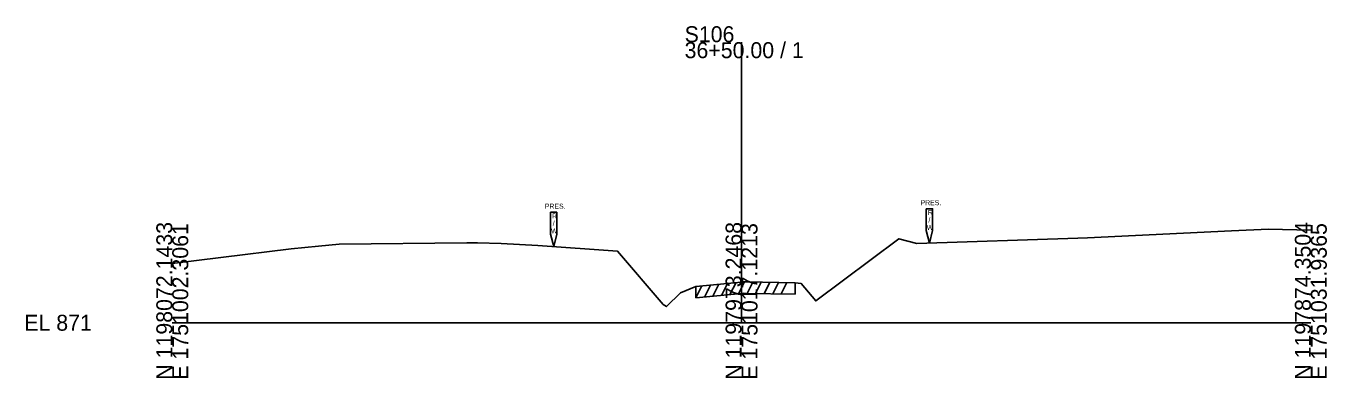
# Model space of a CAD drawing. Extents: x -26 to 1203, y -10 to 19527.
# Drawn here: x 974.3 to 1202.8, y 2990.3 to 3052.1 of the extents above; entities that cross this region are included whole.
import ezdxf

# ---------------------------------------------------------------- set-up
doc = ezdxf.new("R2010")
doc.units = 0
for name, color, linetype in [('RD_GPK_XS_Cell', 7, 'Continuous'), ('RD_XS_ExGround', 7, 'Continuous'), ('RD_XS_ExPaveRet', 7, 'Continuous'), ('RD_XS_ExRW', 7, 'Continuous'), ('RD_XS_TX_Elev_EX', 7, 'Continuous')]:
    doc.layers.add(name, color=color, linetype=linetype)

msp = doc.modelspace()

# ---------------------------------------------------------------- linework, layer by layer
at = {"layer": 'RD_GPK_XS_Cell'}
for p, q in [((1100, 3000), (1100, 3049.24)), ((1000, 3000), (1100, 3000)), ((1100, 3000), (1200, 3000))]:
    msp.add_line(p, q, dxfattribs=at)
at = {"layer": 'RD_XS_ExGround'}
msp.add_lwpolyline([(1000, 3010.38), (1008.53, 3011.43), (1020.91, 3012.95), (1025.68, 3013.45), (1029.32, 3013.81), (1051.72, 3014.03), (1053.59, 3014.05), (1057.8, 3013.88), (1064.23, 3013.58), (1078.23, 3012.54), (1086.25, 3003.23), (1086.79, 3002.85), (1089.26, 3005.23), (1091.97, 3006.36), (1100, 3007.13), (1100.36, 3007.17), (1100.79, 3007.16), (1109.43, 3007.02), (1110.49, 3006.88), (1113.04, 3003.83), (1127.63, 3014.75), (1130.81, 3013.91), (1159.05, 3014.87), (1160.78, 3014.92), (1186.06, 3016.11), (1192.56, 3016.4), (1200, 3016.27)], dxfattribs=at)
at = {"layer": 'RD_XS_ExPaveRet'}
for p, q in [((1091.97, 3004.36), (1093.03, 3006.46)), ((1091.97, 3004.36), (1091.97, 3006.36)), ((1093.47, 3004.5), (1094.53, 3006.6)), ((1094.97, 3004.65), (1096.03, 3006.75)), ((1096.47, 3004.79), (1097.53, 3006.89)), ((1097.97, 3004.94), (1099.03, 3007.04)), ((1099.47, 3005.08), (1100.52, 3007.16)), ((1100.97, 3005.15), (1101.97, 3007.14)), ((1102.47, 3005.13), (1103.47, 3007.11)), ((1103.97, 3005.11), (1104.97, 3007.09)), ((1105.47, 3005.08), (1106.47, 3007.07)), ((1106.97, 3005.06), (1107.97, 3007.04)), ((1109.43, 3007.02), (1109.43, 3005.02)), ((1091.97, 3004.36), (1100, 3005.13)), ((1100, 3005.13), (1100.36, 3005.17)), ((1100.36, 3005.17), (1100.79, 3005.16)), ((1100.79, 3005.16), (1109.43, 3005.02))]:
    msp.add_line(p, q, dxfattribs=at)
at = {"layer": 'RD_XS_ExRW'}
for points in [[(1066.45, 3019.39), (1067.55, 3019.39), (1067.55, 3015.56), (1067, 3013.37), (1066.45, 3015.56)], [(1132.45, 3020), (1133.55, 3020), (1133.55, 3016.18), (1133, 3013.99), (1132.45, 3016.18)]]:
    msp.add_lwpolyline(points, close=True, dxfattribs=at)

# ---------------------------------------------------------------- texts
at = {"layer": 'RD_GPK_XS_Cell'}
for s, p in [('S106', (1090, 3049.24)), ('36+50.00 / 1', (1090, 3046.44)), ('EL 871', (974, 2998.6))]:
    msp.add_text(s, height=2.8, dxfattribs=at).set_placement(p)
for s, p in [('N 1198072.1433', (1000, 2990)), ('E 1751002.3061', (1002.8, 2990)), ('N 1197973.2468', (1100, 2990)), ('E 1751017.1213', (1102.8, 2990)), ('N 1197874.3504', (1200, 2990)), ('E 1751031.9365', (1202.8, 2990))]:
    msp.add_text(s, height=2.8, rotation=90, dxfattribs=at).set_placement(p)
at = {"layer": 'RD_XS_ExRW'}
for s, p in [('PRES.', (1131.45, 3020.63)), ('PRES.', (1065.45, 3020.02)), ('R', (1066.71, 3018.3)), ('R', (1132.71, 3018.91)), ('/', (1066.83, 3016.99)), ('W', (1132.53, 3016.29)), ('/', (1132.83, 3017.6)), ('W', (1066.53, 3015.67))]:
    msp.add_text(s, height=0.875, dxfattribs=at).set_placement(p)
at = {"layer": 'RD_XS_TX_Elev_EX'}
msp.add_text('874.57', height=0.0975, rotation=90, dxfattribs=at).set_placement((1100.1, 3007.13))

doc.saveas('drawing.dxf')
